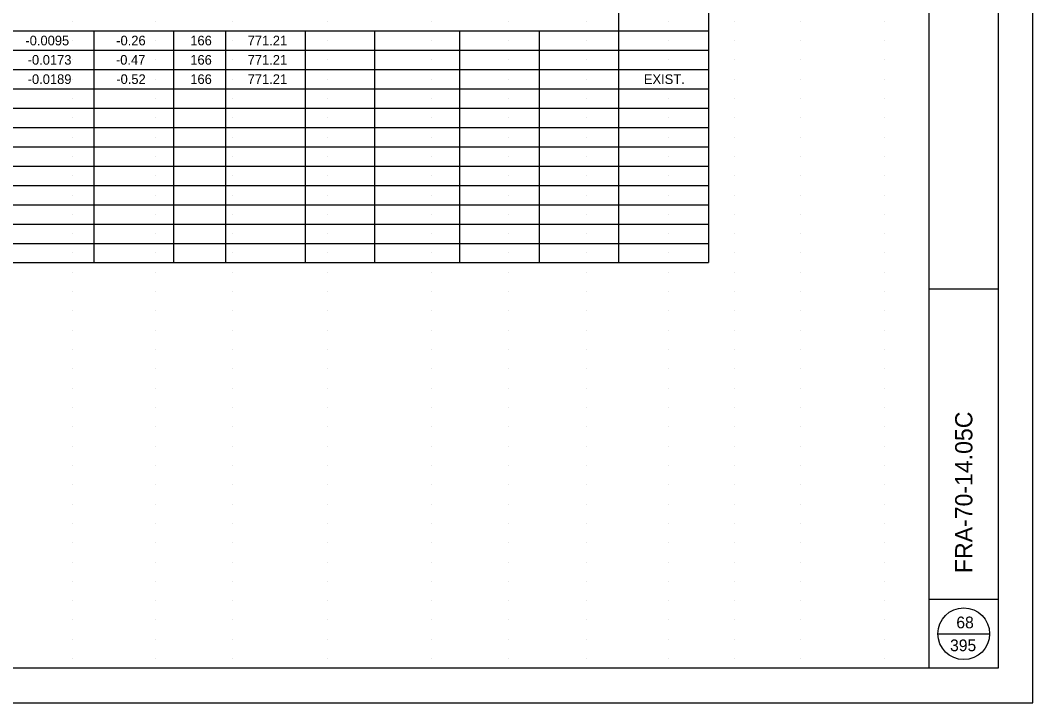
# Model space of a CAD drawing. Extents: x -15.4 to 18.6, y -12.6 to 9.4.
# Drawn here: x 3.96 to 18.64, y -12.61 to -2.72 of the extents above; entities that cross this region are included whole.
import ezdxf

# ---------------------------------------------------------------- set-up
doc = ezdxf.new("R2010")
doc.units = 0
for name, color, linetype in [('SH_Border', 7, 'Continuous'), ('SH_Cut_Line', 7, 'Continuous'), ('SH_Data', 7, 'Continuous'), ('SH_Text', 7, 'Continuous')]:
    doc.layers.add(name, color=color, linetype=linetype)

msp = doc.modelspace()

# ---------------------------------------------------------------- linework, layer by layer
at = {"layer": 'SH_Border'}
for p, q in [((17.143, -12.112), (17.143, 8.888)), ((17.143, -6.612), (18.143, -6.612)), ((17.143, -11.112), (18.143, -11.112))]:
    msp.add_line(p, q, dxfattribs=at)
msp.add_lwpolyline([(-13.357, 8.888), (18.143, 8.888), (18.143, -12.112), (-13.357, -12.112)], close=True, dxfattribs=at)
at = {"layer": 'SH_Cut_Line'}
msp.add_lwpolyline([(-15.357, -12.612), (18.643, -12.612), (18.643, 9.388), (-15.357, 9.388)], close=True, dxfattribs=at)
at = {"layer": 'SH_Data'}
for p, q in [((13.939, 8.888), (13.939, -6.232)), ((12.637, 7.208), (12.637, -6.232)), ((4.718, -2.732), (4.718, -2.732)), ((5.918, -2.732), (5.918, -2.732)), ((7.043, -2.732), (7.043, -2.732)), ((8.418, -2.732), (8.418, -2.732)), ((9.918, -2.732), (9.918, -2.732)), ((11.043, -2.732), (11.043, -2.732)), ((12.168, -2.732), (12.168, -2.732)), ((13.368, -2.732), (13.368, -2.732)), ((14.318, -2.732), (14.318, -2.732)), ((15.268, -2.732), (15.268, -2.732)), ((16.493, -2.732), (16.493, -2.732)), ((-10.059, -2.872), (13.939, -2.872)), ((5.028, -2.872), (5.028, -6.232)), ((6.181, -2.872), (6.181, -6.232)), ((6.939, -2.872), (6.939, -6.232)), ((8.092, -2.872), (8.092, -6.232)), ((9.096, -2.872), (9.096, -6.232)), ((10.332, -2.872), (10.332, -6.232)), ((11.484, -2.872), (11.484, -6.232)), ((4.718, -3.012), (4.718, -3.012)), ((5.918, -3.012), (5.918, -3.012)), ((7.043, -3.012), (7.043, -3.012)), ((8.418, -3.012), (8.418, -3.012)), ((9.918, -3.012), (9.918, -3.012)), ((11.043, -3.012), (11.043, -3.012)), ((12.168, -3.012), (12.168, -3.012)), ((13.368, -3.012), (13.368, -3.012)), ((14.318, -3.012), (14.318, -3.012)), ((15.268, -3.012), (15.268, -3.012)), ((16.493, -3.012), (16.493, -3.012)), ((-10.059, -3.152), (13.939, -3.152)), ((4.718, -3.292), (4.718, -3.292)), ((5.918, -3.292), (5.918, -3.292)), ((7.043, -3.292), (7.043, -3.292)), ((8.418, -3.292), (8.418, -3.292)), ((9.918, -3.292), (9.918, -3.292)), ((11.043, -3.292), (11.043, -3.292)), ((12.168, -3.292), (12.168, -3.292)), ((13.368, -3.292), (13.368, -3.292)), ((14.318, -3.292), (14.318, -3.292)), ((15.268, -3.292), (15.268, -3.292)), ((16.493, -3.292), (16.493, -3.292)), ((-10.059, -3.432), (13.939, -3.432)), ((4.718, -3.572), (4.718, -3.572)), ((5.918, -3.572), (5.918, -3.572)), ((7.043, -3.572), (7.043, -3.572)), ((8.418, -3.572), (8.418, -3.572)), ((9.918, -3.572), (9.918, -3.572)), ((11.043, -3.572), (11.043, -3.572)), ((12.168, -3.572), (12.168, -3.572)), ((13.368, -3.572), (13.368, -3.572)), ((14.318, -3.572), (14.318, -3.572)), ((15.268, -3.572), (15.268, -3.572)), ((16.493, -3.572), (16.493, -3.572)), ((-10.059, -3.712), (13.939, -3.712)), ((4.718, -3.852), (4.718, -3.852)), ((5.918, -3.852), (5.918, -3.852)), ((7.043, -3.852), (7.043, -3.852)), ((8.418, -3.852), (8.418, -3.852)), ((9.918, -3.852), (9.918, -3.852)), ((11.043, -3.852), (11.043, -3.852)), ((12.168, -3.852), (12.168, -3.852)), ((13.368, -3.852), (13.368, -3.852)), ((14.318, -3.852), (14.318, -3.852)), ((15.268, -3.852), (15.268, -3.852)), ((16.493, -3.852), (16.493, -3.852)), ((-10.059, -3.992), (13.939, -3.992)), ((4.718, -4.132), (4.718, -4.132)), ((5.918, -4.132), (5.918, -4.132)), ((7.043, -4.132), (7.043, -4.132)), ((8.418, -4.132), (8.418, -4.132)), ((9.918, -4.132), (9.918, -4.132)), ((11.043, -4.132), (11.043, -4.132)), ((12.168, -4.132), (12.168, -4.132)), ((13.368, -4.132), (13.368, -4.132)), ((14.318, -4.132), (14.318, -4.132)), ((15.268, -4.132), (15.268, -4.132)), ((16.493, -4.132), (16.493, -4.132)), ((-10.059, -4.272), (13.939, -4.272)), ((4.718, -4.412), (4.718, -4.412)), ((5.918, -4.412), (5.918, -4.412)), ((7.043, -4.412), (7.043, -4.412)), ((8.418, -4.412), (8.418, -4.412)), ((9.918, -4.412), (9.918, -4.412)), ((11.043, -4.412), (11.043, -4.412)), ((12.168, -4.412), (12.168, -4.412)), ((13.368, -4.412), (13.368, -4.412)), ((14.318, -4.412), (14.318, -4.412)), ((15.268, -4.412), (15.268, -4.412)), ((16.493, -4.412), (16.493, -4.412)), ((-10.059, -4.552), (13.939, -4.552)), ((4.718, -4.692), (4.718, -4.692)), ((5.918, -4.692), (5.918, -4.692)), ((7.043, -4.692), (7.043, -4.692)), ((8.418, -4.692), (8.418, -4.692)), ((9.918, -4.692), (9.918, -4.692)), ((11.043, -4.692), (11.043, -4.692)), ((12.168, -4.692), (12.168, -4.692)), ((13.368, -4.692), (13.368, -4.692)), ((14.318, -4.692), (14.318, -4.692)), ((15.268, -4.692), (15.268, -4.692)), ((16.493, -4.692), (16.493, -4.692)), ((-10.059, -4.832), (13.939, -4.832)), ((4.718, -4.972), (4.718, -4.972)), ((5.918, -4.972), (5.918, -4.972)), ((7.043, -4.972), (7.043, -4.972)), ((8.418, -4.972), (8.418, -4.972)), ((9.918, -4.972), (9.918, -4.972)), ((11.043, -4.972), (11.043, -4.972)), ((12.168, -4.972), (12.168, -4.972)), ((13.368, -4.972), (13.368, -4.972)), ((14.318, -4.972), (14.318, -4.972)), ((15.268, -4.972), (15.268, -4.972)), ((16.493, -4.972), (16.493, -4.972)), ((-10.059, -5.112), (13.939, -5.112)), ((4.718, -5.252), (4.718, -5.252)), ((5.918, -5.252), (5.918, -5.252)), ((7.043, -5.252), (7.043, -5.252)), ((8.418, -5.252), (8.418, -5.252)), ((9.918, -5.252), (9.918, -5.252)), ((11.043, -5.252), (11.043, -5.252)), ((12.168, -5.252), (12.168, -5.252)), ((13.368, -5.252), (13.368, -5.252)), ((14.318, -5.252), (14.318, -5.252)), ((15.268, -5.252), (15.268, -5.252)), ((16.493, -5.252), (16.493, -5.252)), ((-10.059, -5.392), (13.939, -5.392)), ((4.718, -5.532), (4.718, -5.532)), ((5.918, -5.532), (5.918, -5.532)), ((7.043, -5.532), (7.043, -5.532)), ((8.418, -5.532), (8.418, -5.532)), ((9.918, -5.532), (9.918, -5.532)), ((11.043, -5.532), (11.043, -5.532)), ((12.168, -5.532), (12.168, -5.532)), ((13.368, -5.532), (13.368, -5.532)), ((14.318, -5.532), (14.318, -5.532)), ((15.268, -5.532), (15.268, -5.532)), ((16.493, -5.532), (16.493, -5.532)), ((-10.059, -5.672), (13.939, -5.672)), ((4.718, -5.812), (4.718, -5.812)), ((5.918, -5.812), (5.918, -5.812)), ((7.043, -5.812), (7.043, -5.812)), ((8.418, -5.812), (8.418, -5.812)), ((9.918, -5.812), (9.918, -5.812)), ((11.043, -5.812), (11.043, -5.812)), ((12.168, -5.812), (12.168, -5.812)), ((13.368, -5.812), (13.368, -5.812)), ((14.318, -5.812), (14.318, -5.812)), ((15.268, -5.812), (15.268, -5.812)), ((16.493, -5.812), (16.493, -5.812)), ((-10.059, -5.952), (13.939, -5.952)), ((4.718, -6.092), (4.718, -6.092)), ((5.918, -6.092), (5.918, -6.092)), ((7.043, -6.092), (7.043, -6.092)), ((8.418, -6.092), (8.418, -6.092)), ((9.918, -6.092), (9.918, -6.092)), ((11.043, -6.092), (11.043, -6.092)), ((12.168, -6.092), (12.168, -6.092)), ((13.368, -6.092), (13.368, -6.092)), ((14.318, -6.092), (14.318, -6.092)), ((15.268, -6.092), (15.268, -6.092)), ((16.493, -6.092), (16.493, -6.092)), ((-10.059, -6.232), (13.939, -6.232)), ((4.718, -6.372), (4.718, -6.372)), ((5.918, -6.372), (5.918, -6.372)), ((7.043, -6.372), (7.043, -6.372)), ((8.418, -6.372), (8.418, -6.372)), ((9.918, -6.372), (9.918, -6.372)), ((11.043, -6.372), (11.043, -6.372)), ((12.168, -6.372), (12.168, -6.372)), ((13.368, -6.372), (13.368, -6.372)), ((14.318, -6.372), (14.318, -6.372)), ((15.268, -6.372), (15.268, -6.372)), ((16.493, -6.372), (16.493, -6.372)), ((4.718, -6.652), (4.718, -6.652)), ((5.918, -6.652), (5.918, -6.652)), ((7.043, -6.652), (7.043, -6.652)), ((8.418, -6.652), (8.418, -6.652)), ((9.918, -6.652), (9.918, -6.652)), ((11.043, -6.652), (11.043, -6.652)), ((12.168, -6.652), (12.168, -6.652)), ((13.368, -6.652), (13.368, -6.652)), ((14.318, -6.652), (14.318, -6.652)), ((15.268, -6.652), (15.268, -6.652)), ((16.493, -6.652), (16.493, -6.652)), ((4.718, -6.932), (4.718, -6.932)), ((5.918, -6.932), (5.918, -6.932)), ((7.043, -6.932), (7.043, -6.932)), ((8.418, -6.932), (8.418, -6.932)), ((9.918, -6.932), (9.918, -6.932)), ((11.043, -6.932), (11.043, -6.932)), ((12.168, -6.932), (12.168, -6.932)), ((13.368, -6.932), (13.368, -6.932)), ((14.318, -6.932), (14.318, -6.932)), ((15.268, -6.932), (15.268, -6.932)), ((16.493, -6.932), (16.493, -6.932)), ((4.718, -7.212), (4.718, -7.212)), ((5.918, -7.212), (5.918, -7.212)), ((7.043, -7.212), (7.043, -7.212)), ((8.418, -7.212), (8.418, -7.212)), ((9.918, -7.212), (9.918, -7.212)), ((11.043, -7.212), (11.043, -7.212)), ((12.168, -7.212), (12.168, -7.212)), ((13.368, -7.212), (13.368, -7.212)), ((14.318, -7.212), (14.318, -7.212)), ((15.268, -7.212), (15.268, -7.212)), ((16.493, -7.212), (16.493, -7.212)), ((4.718, -7.492), (4.718, -7.492)), ((5.918, -7.492), (5.918, -7.492)), ((7.043, -7.492), (7.043, -7.492)), ((8.418, -7.492), (8.418, -7.492)), ((9.918, -7.492), (9.918, -7.492)), ((11.043, -7.492), (11.043, -7.492)), ((12.168, -7.492), (12.168, -7.492)), ((13.368, -7.492), (13.368, -7.492)), ((14.318, -7.492), (14.318, -7.492)), ((15.268, -7.492), (15.268, -7.492)), ((16.493, -7.492), (16.493, -7.492)), ((4.718, -7.772), (4.718, -7.772)), ((5.918, -7.772), (5.918, -7.772)), ((7.043, -7.772), (7.043, -7.772)), ((8.418, -7.772), (8.418, -7.772)), ((9.918, -7.772), (9.918, -7.772)), ((11.043, -7.772), (11.043, -7.772)), ((12.168, -7.772), (12.168, -7.772)), ((13.368, -7.772), (13.368, -7.772)), ((14.318, -7.772), (14.318, -7.772)), ((15.268, -7.772), (15.268, -7.772)), ((16.493, -7.772), (16.493, -7.772)), ((4.718, -8.052), (4.718, -8.052)), ((5.918, -8.052), (5.918, -8.052)), ((7.043, -8.052), (7.043, -8.052)), ((8.418, -8.052), (8.418, -8.052)), ((9.918, -8.052), (9.918, -8.052)), ((11.043, -8.052), (11.043, -8.052)), ((12.168, -8.052), (12.168, -8.052)), ((13.368, -8.052), (13.368, -8.052)), ((14.318, -8.052), (14.318, -8.052)), ((15.268, -8.052), (15.268, -8.052)), ((16.493, -8.052), (16.493, -8.052)), ((4.718, -8.332), (4.718, -8.332)), ((5.918, -8.332), (5.918, -8.332)), ((7.043, -8.332), (7.043, -8.332)), ((8.418, -8.332), (8.418, -8.332)), ((9.918, -8.332), (9.918, -8.332)), ((11.043, -8.332), (11.043, -8.332)), ((12.168, -8.332), (12.168, -8.332)), ((13.368, -8.332), (13.368, -8.332)), ((14.318, -8.332), (14.318, -8.332)), ((15.268, -8.332), (15.268, -8.332)), ((16.493, -8.332), (16.493, -8.332)), ((4.718, -8.612), (4.718, -8.612)), ((5.918, -8.612), (5.918, -8.612)), ((7.043, -8.612), (7.043, -8.612)), ((8.418, -8.612), (8.418, -8.612)), ((9.918, -8.612), (9.918, -8.612)), ((11.043, -8.612), (11.043, -8.612)), ((12.168, -8.612), (12.168, -8.612)), ((13.368, -8.612), (13.368, -8.612)), ((14.318, -8.612), (14.318, -8.612)), ((15.268, -8.612), (15.268, -8.612)), ((16.493, -8.612), (16.493, -8.612)), ((4.718, -8.892), (4.718, -8.892)), ((5.918, -8.892), (5.918, -8.892)), ((7.043, -8.892), (7.043, -8.892)), ((8.418, -8.892), (8.418, -8.892)), ((9.918, -8.892), (9.918, -8.892)), ((11.043, -8.892), (11.043, -8.892)), ((12.168, -8.892), (12.168, -8.892)), ((13.368, -8.892), (13.368, -8.892)), ((14.318, -8.892), (14.318, -8.892)), ((15.268, -8.892), (15.268, -8.892)), ((16.493, -8.892), (16.493, -8.892)), ((4.718, -9.172), (4.718, -9.172)), ((5.918, -9.172), (5.918, -9.172)), ((7.043, -9.172), (7.043, -9.172)), ((8.418, -9.172), (8.418, -9.172)), ((9.918, -9.172), (9.918, -9.172)), ((11.043, -9.172), (11.043, -9.172)), ((12.168, -9.172), (12.168, -9.172)), ((13.368, -9.172), (13.368, -9.172)), ((14.318, -9.172), (14.318, -9.172)), ((15.268, -9.172), (15.268, -9.172)), ((16.493, -9.172), (16.493, -9.172)), ((4.718, -9.452), (4.718, -9.452)), ((5.918, -9.452), (5.918, -9.452)), ((7.043, -9.452), (7.043, -9.452)), ((8.418, -9.452), (8.418, -9.452)), ((9.918, -9.452), (9.918, -9.452)), ((11.043, -9.452), (11.043, -9.452)), ((12.168, -9.452), (12.168, -9.452)), ((13.368, -9.452), (13.368, -9.452)), ((14.318, -9.452), (14.318, -9.452)), ((15.268, -9.452), (15.268, -9.452)), ((16.493, -9.452), (16.493, -9.452)), ((4.718, -9.732), (4.718, -9.732)), ((5.918, -9.732), (5.918, -9.732)), ((7.043, -9.732), (7.043, -9.732)), ((8.418, -9.732), (8.418, -9.732)), ((9.918, -9.732), (9.918, -9.732)), ((11.043, -9.732), (11.043, -9.732)), ((12.168, -9.732), (12.168, -9.732)), ((13.368, -9.732), (13.368, -9.732)), ((14.318, -9.732), (14.318, -9.732)), ((15.268, -9.732), (15.268, -9.732)), ((16.493, -9.732), (16.493, -9.732)), ((4.718, -10.012), (4.718, -10.012)), ((5.918, -10.012), (5.918, -10.012)), ((7.043, -10.012), (7.043, -10.012)), ((8.418, -10.012), (8.418, -10.012)), ((9.918, -10.012), (9.918, -10.012)), ((11.043, -10.012), (11.043, -10.012)), ((12.168, -10.012), (12.168, -10.012)), ((13.368, -10.012), (13.368, -10.012)), ((14.318, -10.012), (14.318, -10.012)), ((15.268, -10.012), (15.268, -10.012)), ((16.493, -10.012), (16.493, -10.012)), ((4.718, -10.292), (4.718, -10.292)), ((5.918, -10.292), (5.918, -10.292)), ((7.043, -10.292), (7.043, -10.292)), ((8.418, -10.292), (8.418, -10.292)), ((9.918, -10.292), (9.918, -10.292)), ((11.043, -10.292), (11.043, -10.292)), ((12.168, -10.292), (12.168, -10.292)), ((13.368, -10.292), (13.368, -10.292)), ((14.318, -10.292), (14.318, -10.292)), ((15.268, -10.292), (15.268, -10.292)), ((16.493, -10.292), (16.493, -10.292)), ((4.718, -10.572), (4.718, -10.572)), ((5.918, -10.572), (5.918, -10.572)), ((7.043, -10.572), (7.043, -10.572)), ((8.418, -10.572), (8.418, -10.572)), ((9.918, -10.572), (9.918, -10.572)), ((11.043, -10.572), (11.043, -10.572)), ((12.168, -10.572), (12.168, -10.572)), ((13.368, -10.572), (13.368, -10.572)), ((14.318, -10.572), (14.318, -10.572)), ((15.268, -10.572), (15.268, -10.572)), ((16.493, -10.572), (16.493, -10.572)), ((4.718, -10.852), (4.718, -10.852)), ((5.918, -10.852), (5.918, -10.852)), ((7.043, -10.852), (7.043, -10.852)), ((8.418, -10.852), (8.418, -10.852)), ((9.918, -10.852), (9.918, -10.852)), ((11.043, -10.852), (11.043, -10.852)), ((12.168, -10.852), (12.168, -10.852)), ((13.368, -10.852), (13.368, -10.852)), ((14.318, -10.852), (14.318, -10.852)), ((15.268, -10.852), (15.268, -10.852)), ((16.493, -10.852), (16.493, -10.852)), ((4.718, -11.132), (4.718, -11.132)), ((5.918, -11.132), (5.918, -11.132)), ((7.043, -11.132), (7.043, -11.132)), ((8.418, -11.132), (8.418, -11.132)), ((9.918, -11.132), (9.918, -11.132)), ((11.043, -11.132), (11.043, -11.132)), ((12.168, -11.132), (12.168, -11.132)), ((13.368, -11.132), (13.368, -11.132)), ((14.318, -11.132), (14.318, -11.132)), ((15.268, -11.132), (15.268, -11.132)), ((16.493, -11.132), (16.493, -11.132)), ((4.718, -11.412), (4.718, -11.412)), ((5.918, -11.412), (5.918, -11.412)), ((7.043, -11.412), (7.043, -11.412)), ((8.418, -11.412), (8.418, -11.412)), ((9.918, -11.412), (9.918, -11.412)), ((11.043, -11.412), (11.043, -11.412)), ((12.168, -11.412), (12.168, -11.412)), ((13.368, -11.412), (13.368, -11.412)), ((14.318, -11.412), (14.318, -11.412)), ((15.268, -11.412), (15.268, -11.412)), ((16.493, -11.412), (16.493, -11.412)), ((4.718, -11.692), (4.718, -11.692)), ((5.918, -11.692), (5.918, -11.692)), ((7.043, -11.692), (7.043, -11.692)), ((8.418, -11.692), (8.418, -11.692)), ((9.918, -11.692), (9.918, -11.692)), ((11.043, -11.692), (11.043, -11.692)), ((12.168, -11.692), (12.168, -11.692)), ((13.368, -11.692), (13.368, -11.692)), ((14.318, -11.692), (14.318, -11.692)), ((15.268, -11.692), (15.268, -11.692)), ((16.493, -11.692), (16.493, -11.692)), ((17.268, -11.612), (18.018, -11.612)), ((4.718, -11.972), (4.718, -11.972)), ((5.918, -11.972), (5.918, -11.972)), ((7.043, -11.972), (7.043, -11.972)), ((8.418, -11.972), (8.418, -11.972)), ((9.918, -11.972), (9.918, -11.972)), ((11.043, -11.972), (11.043, -11.972)), ((12.168, -11.972), (12.168, -11.972)), ((13.368, -11.972), (13.368, -11.972)), ((14.318, -11.972), (14.318, -11.972)), ((15.268, -11.972), (15.268, -11.972)), ((16.493, -11.972), (16.493, -11.972))]:
    msp.add_line(p, q, dxfattribs=at)
msp.add_circle((17.643, -11.612), 0.375, dxfattribs=at)

# ---------------------------------------------------------------- texts
msp.add_text(' FRA-70-14.05C  ', height=0.25, rotation=90, dxfattribs=at).set_placement((17.768, -10.825))
for s, p in [('68', (17.535, -11.533)), ('395', (17.444, -11.865))]:
    msp.add_text(s, height=0.17, dxfattribs=at).set_placement(p)
at = {"layer": 'SH_Text'}
for s, p in [('-0.0095', (4.035, -3.082)), ('-0.26', (5.352, -3.082)), ('166', (6.426, -3.082)), ('771.21', (7.258, -3.082)), ('-0.0173', (4.068, -3.362)), ('-0.47', (5.348, -3.362)), ('166', (6.426, -3.362)), ('771.21', (7.258, -3.362)), ('-0.0189', (4.068, -3.642)), ('-0.52', (5.353, -3.642)), ('166', (6.426, -3.642)), ('771.21', (7.258, -3.642)), ('EXIST.', (13.004, -3.642))]:
    msp.add_text(s, height=0.14, dxfattribs=at).set_placement(p)

doc.saveas('drawing.dxf')
